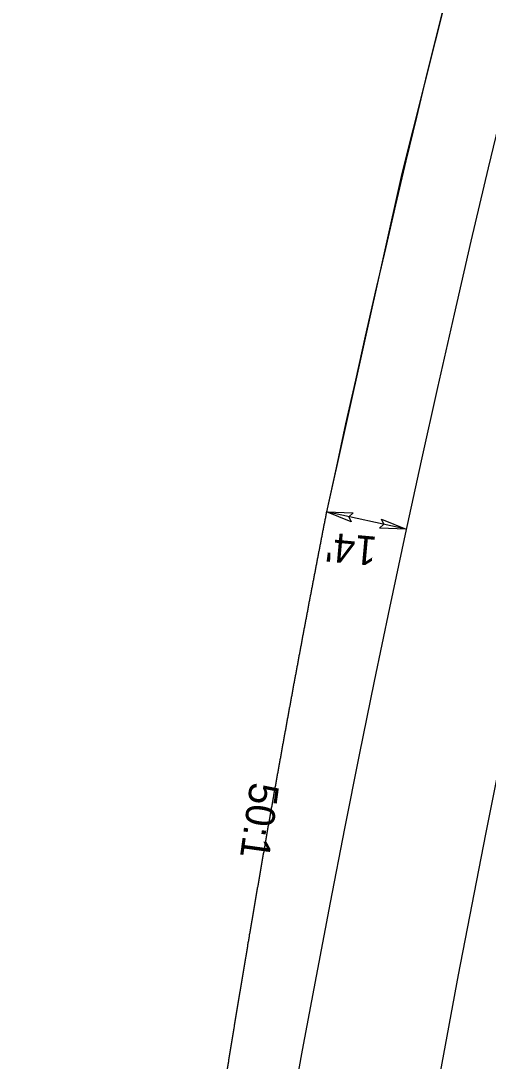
# Model space of a CAD drawing. Extents: x 2389694 to 2405615, y 546931 to 573532.
# Drawn here: x 2400104.7 to 2400184.8, y 568563.8 to 568742.4 of the extents above; entities that cross this region are included whole.
import ezdxf

# ---------------------------------------------------------------- set-up
doc = ezdxf.new("R2010")
doc.units = 0
for name, color, linetype in [('Prop Dimension', 7, 'Continuous'), ('Prop Dimension Text', 7, 'Continuous'), ('Prop EOT', 7, 'Continuous'), ('Prop Guardrail', 7, 'Continuous'), ('Prop Horizontal Alignment', 7, 'Continuous')]:
    doc.layers.add(name, color=color, linetype=linetype)

msp = doc.modelspace()

# ---------------------------------------------------------------- linework, layer by layer
at = {"layer": 'Prop Dimension'}
msp.add_line((2400170.81, 568655.14), (2400157.12, 568658.09), dxfattribs=at)
for points in [[(2400161.36, 568656.38), (2400157.12, 568658.09), (2400161.71, 568657.92), (2400160.98, 568657.25)], [(2400166.57, 568656.84), (2400170.81, 568655.14), (2400166.21, 568655.31), (2400166.94, 568655.97)]]:
    msp.add_lwpolyline(points, close=True, dxfattribs=at)
at = {"layer": 'Prop EOT'}
for radius, start, end in [(2923, 119.41161, 180.94658), (2877, 119.41161, 180.94658), (2961, 148.75529, 167.84172), (2947, 148.75529, 180.94658)]:
    msp.add_arc((2403051.7, 568034.46), radius, start, end, dxfattribs=at)
for points in [[(2400157.12, 568658.09), (2400156.99, 568657.41), (2400156.86, 568656.73), (2400156.72, 568656.05), (2400156.59, 568655.38), (2400156.46, 568654.7), (2400156.33, 568654.03), (2400156.2, 568653.34), (2400156.07, 568652.67), (2400155.94, 568651.99), (2400155.81, 568651.31), (2400155.68, 568650.64), (2400155.55, 568649.96), (2400155.42, 568649.28), (2400155.29, 568648.6), (2400155.16, 568647.93), (2400155.03, 568647.25), (2400154.9, 568646.57), (2400154.77, 568645.89), (2400154.64, 568645.21), (2400154.51, 568644.54), (2400154.38, 568643.86), (2400154.25, 568643.19), (2400154.12, 568642.5), (2400153.99, 568641.82), (2400153.87, 568641.15), (2400153.74, 568640.47), (2400153.61, 568639.79), (2400153.48, 568639.11), (2400153.36, 568638.44), (2400153.23, 568637.76), (2400153.1, 568637.07), (2400152.97, 568636.4), (2400152.85, 568635.72), (2400152.72, 568635.05), (2400152.59, 568634.36), (2400152.47, 568633.69), (2400152.34, 568633.01), (2400152.22, 568632.34), (2400152.09, 568631.65), (2400151.96, 568630.97), (2400151.84, 568630.3), (2400151.71, 568629.62), (2400151.59, 568628.94), (2400151.46, 568628.26), (2400151.34, 568627.59), (2400151.21, 568626.9), (2400151.09, 568626.22), (2400150.96, 568625.55), (2400150.84, 568624.87), (2400150.71, 568624.19), (2400150.59, 568623.51), (2400150.47, 568622.84), (2400150.34, 568622.15), (2400150.22, 568621.47), (2400150.1, 568620.8), (2400149.97, 568620.12), (2400149.85, 568619.44), (2400149.73, 568618.76), (2400149.6, 568618.09), (2400149.48, 568617.4), (2400149.36, 568616.72), (2400149.24, 568616.05), (2400149.11, 568615.36), (2400148.99, 568614.69), (2400148.87, 568614.01), (2400148.75, 568613.33), (2400148.63, 568612.65), (2400148.5, 568611.97), (2400148.38, 568611.29), (2400148.26, 568610.61), (2400148.14, 568609.94), (2400148.02, 568609.25), (2400147.9, 568608.58), (2400147.78, 568607.9)], [(2400147.78, 568607.9), (2400147.66, 568607.21), (2400147.54, 568606.54), (2400147.42, 568605.86), (2400147.3, 568605.18), (2400147.18, 568604.5), (2400147.06, 568603.82), (2400146.94, 568603.14), (2400146.82, 568602.47), (2400146.7, 568601.78), (2400146.58, 568601.1), (2400146.47, 568600.43), (2400146.35, 568599.74), (2400146.23, 568599.07), (2400146.11, 568598.38), (2400145.99, 568597.71), (2400145.87, 568597.03), (2400145.76, 568596.34), (2400145.64, 568595.67), (2400145.52, 568594.98), (2400145.41, 568594.31), (2400145.29, 568593.63), (2400145.17, 568592.95), (2400145.05, 568592.27), (2400144.94, 568591.58), (2400144.82, 568590.91), (2400144.7, 568590.23), (2400144.59, 568589.55), (2400144.47, 568588.87), (2400144.36, 568588.19), (2400144.24, 568587.51), (2400144.12, 568586.82), (2400144.01, 568586.15), (2400143.89, 568585.47), (2400143.78, 568584.79), (2400143.66, 568584.11), (2400143.55, 568583.43), (2400143.44, 568582.75), (2400143.32, 568582.06), (2400143.21, 568581.39), (2400143.09, 568580.7), (2400142.98, 568580.03), (2400142.87, 568579.35), (2400142.75, 568578.67), (2400142.64, 568577.99), (2400142.52, 568577.3), (2400142.41, 568576.63), (2400142.3, 568575.94), (2400142.19, 568575.27), (2400142.07, 568574.58), (2400141.96, 568573.91), (2400141.85, 568573.22), (2400141.74, 568572.55), (2400141.62, 568571.86), (2400141.51, 568571.18), (2400141.4, 568570.51), (2400141.29, 568569.82), (2400141.18, 568569.15), (2400141.07, 568568.46), (2400140.96, 568567.79), (2400140.85, 568567.1), (2400140.73, 568566.42), (2400140.62, 568565.74), (2400140.51, 568565.06), (2400140.4, 568564.38), (2400140.29, 568563.7), (2400140.18, 568563.02), (2400140.07, 568562.33), (2400139.96, 568561.65), (2400139.85, 568560.97), (2400139.74, 568560.29), (2400139.64, 568559.61), (2400139.53, 568558.93), (2400139.31, 568557.57)]]:
    msp.add_spline(points, degree=3, dxfattribs=at)
at = {"layer": 'Prop Guardrail'}
for p, q in [((2400183.16, 568768.33), (2400170.02, 568716.17)), ((2400170.02, 568716.17), (2400157.12, 568658.09))]:
    msp.add_line(p, q, dxfattribs=at)
for points in [[(2400157.12, 568658.09), (2400156.99, 568657.41), (2400156.86, 568656.73), (2400156.72, 568656.05), (2400156.59, 568655.38), (2400156.46, 568654.7), (2400156.33, 568654.03), (2400156.2, 568653.34), (2400156.07, 568652.67), (2400155.94, 568651.99), (2400155.81, 568651.31), (2400155.68, 568650.64), (2400155.55, 568649.96), (2400155.42, 568649.28), (2400155.29, 568648.6), (2400155.16, 568647.93), (2400155.03, 568647.25), (2400154.9, 568646.57), (2400154.77, 568645.89), (2400154.64, 568645.21), (2400154.51, 568644.54), (2400154.38, 568643.86), (2400154.25, 568643.19), (2400154.12, 568642.5), (2400153.99, 568641.82), (2400153.87, 568641.15), (2400153.74, 568640.47), (2400153.61, 568639.79), (2400153.48, 568639.11), (2400153.36, 568638.44), (2400153.23, 568637.76), (2400153.1, 568637.07), (2400152.97, 568636.4), (2400152.85, 568635.72), (2400152.72, 568635.05), (2400152.59, 568634.36), (2400152.47, 568633.69), (2400152.34, 568633.01), (2400152.22, 568632.34), (2400152.09, 568631.65), (2400151.96, 568630.97), (2400151.84, 568630.3), (2400151.71, 568629.62), (2400151.59, 568628.94), (2400151.46, 568628.26), (2400151.34, 568627.59), (2400151.21, 568626.9), (2400151.09, 568626.22), (2400150.96, 568625.55), (2400150.84, 568624.87), (2400150.71, 568624.19), (2400150.59, 568623.51), (2400150.47, 568622.84), (2400150.34, 568622.15), (2400150.22, 568621.47), (2400150.1, 568620.8), (2400149.97, 568620.12), (2400149.85, 568619.44), (2400149.73, 568618.76), (2400149.6, 568618.09), (2400149.48, 568617.4), (2400149.36, 568616.72), (2400149.24, 568616.05), (2400149.11, 568615.36), (2400148.99, 568614.69), (2400148.87, 568614.01), (2400148.75, 568613.33), (2400148.63, 568612.65), (2400148.5, 568611.97), (2400148.38, 568611.29), (2400148.26, 568610.61), (2400148.14, 568609.94), (2400148.02, 568609.25), (2400147.9, 568608.58), (2400147.78, 568607.9)], [(2400147.78, 568607.9), (2400147.66, 568607.21), (2400147.54, 568606.54), (2400147.42, 568605.86), (2400147.3, 568605.18), (2400147.18, 568604.5), (2400147.06, 568603.82), (2400146.94, 568603.14), (2400146.82, 568602.47), (2400146.7, 568601.78), (2400146.58, 568601.1), (2400146.47, 568600.43), (2400146.35, 568599.74), (2400146.23, 568599.07), (2400146.11, 568598.38), (2400145.99, 568597.71), (2400145.87, 568597.03), (2400145.76, 568596.34), (2400145.64, 568595.67), (2400145.52, 568594.98), (2400145.41, 568594.31), (2400145.29, 568593.63), (2400145.17, 568592.95), (2400145.05, 568592.27), (2400144.94, 568591.58), (2400144.82, 568590.91), (2400144.7, 568590.23), (2400144.59, 568589.55), (2400144.47, 568588.87), (2400144.36, 568588.19), (2400144.24, 568587.51), (2400144.12, 568586.82), (2400144.01, 568586.15), (2400143.89, 568585.47), (2400143.78, 568584.79), (2400143.66, 568584.11), (2400143.55, 568583.43), (2400143.44, 568582.75), (2400143.32, 568582.06), (2400143.21, 568581.39), (2400143.09, 568580.7), (2400142.98, 568580.03), (2400142.87, 568579.35), (2400142.75, 568578.67), (2400142.64, 568577.99), (2400142.52, 568577.3), (2400142.41, 568576.63), (2400142.3, 568575.94), (2400142.19, 568575.27), (2400142.07, 568574.58), (2400141.96, 568573.91), (2400141.85, 568573.22), (2400141.74, 568572.55), (2400141.62, 568571.86), (2400141.51, 568571.18), (2400141.4, 568570.51), (2400141.29, 568569.82), (2400141.18, 568569.15), (2400141.07, 568568.46), (2400140.96, 568567.79), (2400140.85, 568567.1), (2400140.73, 568566.42), (2400140.62, 568565.74), (2400140.51, 568565.06), (2400140.4, 568564.38), (2400140.29, 568563.7), (2400140.18, 568563.02), (2400140.07, 568562.33), (2400139.96, 568561.65), (2400139.85, 568560.97), (2400139.74, 568560.29), (2400139.64, 568559.61), (2400139.53, 568558.93), (2400139.31, 568557.57)]]:
    msp.add_spline(points, degree=3, dxfattribs=at)
at = {"layer": 'Prop Horizontal Alignment'}
msp.add_arc((2403051.7, 568034.46), 2900, 119.41161, 180.94658, dxfattribs=at)

# ---------------------------------------------------------------- texts
at = {"layer": 'Prop Dimension Text'}
for s, rotation, p in [("14'", 174.8377, (2400165.93, 568653.78)), ('50:1', 262.1285, (2400144.07, 568611.83))]:
    msp.add_text(s, height=5, rotation=rotation, dxfattribs=at).set_placement(p)

doc.saveas('drawing.dxf')
